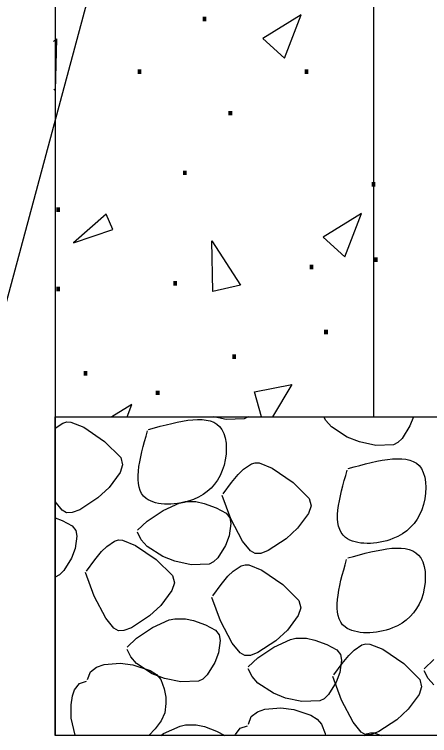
# Model space of a CAD drawing. Extents: x 638447 to 639352, y 298406 to 299000.
# Drawn here: x 638720.23 to 638735.85, y 298690 to 298717.15 of the extents above; entities that cross this region are included whole.
import ezdxf

# ---------------------------------------------------------------- set-up
doc = ezdxf.new("R2010")
doc.units = 0
doc.layers.add('2', color=7, linetype='Continuous')

msp = doc.modelspace()

# ---------------------------------------------------------------- linework, layer by layer
at = {"layer": '2'}
msp.add_line((638721.754375, 298774.004), (638721.754375, 298690.004), dxfattribs=at)
for points in [[(638727.754375, 298774.004), (638721.754375, 298774.004), (638721.754375, 298702.004), (638733.754375, 298702.004), (638733.754375, 298766.248)], [(638714.282375, 298697.684), (638717.588375, 298697.684), (638726.312375, 298730.088)], [(638721.698375, 298716.124), (638721.810375, 298716.222)], [(638721.810375, 298716.222), (638721.762375, 298714.278)], [(638721.762375, 298714.278), (638721.706375, 298714.334)], [(638729.262375, 298702.938), (638730.666375, 298703.214)], [(638730.666375, 298703.214), (638729.936375, 298702.004)], [(638729.528375, 298702.004), (638729.262375, 298702.938)], [(638724.642375, 298702.47), (638723.898375, 298702.004)], [(638724.464375, 298702.004), (638724.642375, 298702.47)], [(638722.050375, 298701.768), (638722.200375, 298701.808)], [(638722.200375, 298701.808), (638722.346375, 298701.802)], [(638722.346375, 298701.802), (638722.836375, 298701.606)], [(638728.202375, 298701.904), (638727.728375, 298702.004)], [(638728.876375, 298701.924), (638728.202375, 298701.904)], [(638729.028375, 298702.004), (638728.876375, 298701.924)], [(638731.948375, 298701.866), (638731.878375, 298702.004)], [(638732.162375, 298701.618), (638731.948375, 298701.866)], [(638735.246375, 298702.004), (638735.114375, 298701.656)], [(638721.754375, 298701.568), (638722.050375, 298701.768)], [(638722.836375, 298701.606), (638723.620375, 298701.068)], [(638732.754375, 298701.232), (638732.162375, 298701.618)], [(638735.114375, 298701.656), (638734.824375, 298701.188)], [(638723.620375, 298701.068), (638724.226375, 298700.464)], [(638733.214375, 298701.056), (638732.754375, 298701.232)], [(638733.828375, 298700.926), (638733.214375, 298701.056)], [(638734.662375, 298701.03), (638734.502375, 298700.946)], [(638734.824375, 298701.188), (638734.662375, 298701.03)], [(638734.502375, 298700.946), (638733.828375, 298700.926)], [(638724.226375, 298700.464), (638724.298375, 298700.19)], [(638724.298375, 298700.19), (638724.206375, 298699.9)], [(638728.846375, 298700.032), (638729.146375, 298700.23)], [(638729.146375, 298700.23), (638729.294375, 298700.272)], [(638729.294375, 298700.272), (638729.440375, 298700.266)], [(638729.440375, 298700.266), (638729.930375, 298700.07)], [(638724.206375, 298699.9), (638723.794375, 298699.344)], [(638728.650375, 298699.836), (638728.846375, 298700.032)], [(638729.930375, 298700.07), (638730.714375, 298699.532)], [(638728.396375, 298699.528), (638728.650375, 298699.836)], [(638723.794375, 298699.344), (638723.364375, 298698.948)], [(638728.084375, 298699.102), (638728.396375, 298699.528)], [(638730.714375, 298699.532), (638731.320375, 298698.928)], [(638722.022375, 298698.49), (638721.754375, 298698.814)], [(638723.364375, 298698.948), (638722.688375, 298698.504)], [(638726.452375, 298698.762), (638726.658375, 298698.812)], [(638726.658375, 298698.812), (638727.056375, 298698.808)], [(638727.056375, 298698.808), (638727.368375, 298698.744)], [(638728.374375, 298698.158), (638728.044375, 298699.044)], [(638731.320375, 298698.928), (638731.392375, 298698.654)], [(638725.828375, 298698.48), (638726.452375, 298698.762)], [(638727.368375, 298698.744), (638727.820375, 298698.578)], [(638727.820375, 298698.578), (638728.198375, 298698.374)], [(638731.392375, 298698.654), (638731.300375, 298698.364)], [(638722.190375, 298698.39), (638722.022375, 298698.49)], [(638722.402375, 298698.396), (638722.190375, 298698.39)], [(638722.688375, 298698.504), (638722.402375, 298698.396)], [(638725.224375, 298698.08), (638725.828375, 298698.48)], [(638728.198375, 298698.374), (638728.332375, 298698.204)], [(638731.300375, 298698.364), (638730.888375, 298697.808)], [(638721.754375, 298698.196), (638722.022375, 298698.098)], [(638722.022375, 298698.098), (638722.400375, 298697.892)], [(638724.862375, 298697.734), (638725.224375, 298698.08)], [(638728.374375, 298697.988), (638728.308375, 298697.528)], [(638728.332375, 298698.204), (638728.374375, 298697.988)], [(638728.810375, 298697.324), (638728.374375, 298698.158)], [(638722.400375, 298697.892), (638722.536375, 298697.722)], [(638722.536375, 298697.722), (638722.578375, 298697.506)], [(638730.888375, 298697.808), (638730.458375, 298697.412)], [(638722.578375, 298697.506), (638722.510375, 298697.046)], [(638725.002375, 298697.374), (638724.862375, 298697.656)], [(638728.308375, 298697.528), (638728.170375, 298697.164)], [(638723.700375, 298697.126), (638723.998375, 298697.326)], [(638723.998375, 298697.326), (638724.148375, 298697.368)], [(638724.148375, 298697.368), (638724.294375, 298697.362)], [(638724.294375, 298697.362), (638724.784375, 298697.164)], [(638725.218375, 298697.126), (638725.002375, 298697.374)], [(638729.116375, 298696.954), (638728.810375, 298697.324)], [(638730.458375, 298697.412), (638729.782375, 298696.968)], [(638722.510375, 298697.046), (638722.372375, 298696.682)], [(638723.250375, 298696.624), (638723.504375, 298696.93)], [(638723.504375, 298696.93), (638723.700375, 298697.126)], [(638724.784375, 298697.164), (638725.568375, 298696.626)], [(638725.810375, 298696.738), (638725.218375, 298697.126)], [(638728.170375, 298697.164), (638727.878375, 298696.696)], [(638729.286375, 298696.854), (638729.116375, 298696.954)], [(638729.782375, 298696.968), (638729.496375, 298696.86)], [(638722.372375, 298696.682), (638722.082375, 298696.214)], [(638725.568375, 298696.626), (638726.174375, 298696.024)], [(638726.270375, 298696.562), (638725.810375, 298696.738)], [(638727.878375, 298696.696), (638727.716375, 298696.538)], [(638729.496375, 298696.86), (638729.286375, 298696.854)], [(638722.936375, 298696.198), (638723.250375, 298696.624)], [(638726.884375, 298696.434), (638726.270375, 298696.562)], [(638727.558375, 298696.454), (638726.884375, 298696.434)], [(638727.716375, 298696.538), (638727.558375, 298696.454)], [(638728.458375, 298696.194), (638728.758375, 298696.392)], [(638728.758375, 298696.392), (638728.906375, 298696.434)], [(638728.906375, 298696.434), (638729.052375, 298696.428)], [(638729.052375, 298696.428), (638729.544375, 298696.23)], [(638722.082375, 298696.214), (638721.920375, 298696.056)], [(638723.228375, 298695.254), (638722.898375, 298696.14)], [(638728.262375, 298695.998), (638728.458375, 298696.194)], [(638729.544375, 298696.23), (638730.328375, 298695.694)], [(638721.762375, 298695.972), (638721.754375, 298695.972)], [(638721.920375, 298696.056), (638721.762375, 298695.972)], [(638726.174375, 298696.024), (638726.246375, 298695.75)], [(638728.008375, 298695.69), (638728.262375, 298695.998)], [(638726.246375, 298695.75), (638726.154375, 298695.46)], [(638727.696375, 298695.264), (638728.008375, 298695.69)], [(638730.328375, 298695.694), (638730.934375, 298695.09)], [(638726.154375, 298695.46), (638725.742375, 298694.904)], [(638723.662375, 298694.42), (638723.228375, 298695.254)], [(638727.986375, 298694.32), (638727.656375, 298695.206)], [(638730.934375, 298695.09), (638731.004375, 298694.816)], [(638725.742375, 298694.904), (638725.312375, 298694.508)], [(638731.004375, 298694.816), (638730.912375, 298694.526)], [(638725.312375, 298694.508), (638724.636375, 298694.064)], [(638730.912375, 298694.526), (638730.502375, 298693.97)], [(638723.970375, 298694.05), (638723.662375, 298694.42)], [(638725.430375, 298694.072), (638726.056375, 298694.354)], [(638726.056375, 298694.354), (638726.260375, 298694.404)], [(638726.260375, 298694.404), (638726.660375, 298694.4)], [(638726.660375, 298694.4), (638726.972375, 298694.336)], [(638726.972375, 298694.336), (638727.422375, 298694.172)], [(638728.422375, 298693.486), (638727.986375, 298694.32)], [(638724.138375, 298693.948), (638723.970375, 298694.05)], [(638724.350375, 298693.954), (638724.138375, 298693.948)], [(638724.636375, 298694.064), (638724.350375, 298693.954)], [(638724.826375, 298693.672), (638725.430375, 298694.072)], [(638727.422375, 298694.172), (638727.800375, 298693.966)], [(638727.800375, 298693.966), (638727.936375, 298693.796)], [(638730.502375, 298693.97), (638730.070375, 298693.574)], [(638724.466375, 298693.326), (638724.826375, 298693.672)], [(638727.936375, 298693.796), (638727.976375, 298693.582)], [(638730.618375, 298693.616), (638730.824375, 298693.668)], [(638730.824375, 298693.668), (638731.222375, 298693.664)], [(638731.222375, 298693.664), (638731.536375, 298693.598)], [(638727.976375, 298693.582), (638727.910375, 298693.12)], [(638728.728375, 298693.116), (638728.422375, 298693.486)], [(638730.070375, 298693.574), (638729.394375, 298693.13)], [(638729.994375, 298693.334), (638730.618375, 298693.616)], [(638731.536375, 298693.598), (638731.986375, 298693.434)], [(638731.986375, 298693.434), (638732.364375, 298693.228)], [(638733.012375, 298693.216), (638733.310375, 298693.414)], [(638733.310375, 298693.414), (638733.458375, 298693.456)], [(638733.458375, 298693.456), (638733.606375, 298693.45)], [(638733.606375, 298693.45), (638734.096375, 298693.252)], [(638724.606375, 298692.966), (638724.466375, 298693.248)], [(638727.910375, 298693.12), (638727.772375, 298692.756)], [(638728.898375, 298693.016), (638728.728375, 298693.116)], [(638729.394375, 298693.13), (638729.110375, 298693.02)], [(638729.390375, 298692.934), (638729.994375, 298693.334)], [(638732.364375, 298693.228), (638732.498375, 298693.058)], [(638732.814375, 298693.02), (638733.012375, 298693.216)], [(638734.096375, 298693.252), (638734.880375, 298692.716)], [(638724.822375, 298692.718), (638724.606375, 298692.966)], [(638729.110375, 298693.02), (638728.898375, 298693.016)], [(638729.028375, 298692.59), (638729.390375, 298692.934)], [(638732.540375, 298692.844), (638732.474375, 298692.384)], [(638732.498375, 298693.058), (638732.540375, 298692.844)], [(638732.560375, 298692.712), (638732.814375, 298693.02)], [(638735.656375, 298692.518), (638736.016375, 298692.864)], [(638723.084375, 298692.406), (638723.316375, 298692.58)], [(638723.316375, 298692.58), (638723.600375, 298692.676)], [(638723.600375, 298692.676), (638724.202375, 298692.724)], [(638724.202375, 298692.724), (638724.684375, 298692.668)], [(638724.684375, 298692.668), (638725.330375, 298692.456)], [(638725.414375, 298692.332), (638724.822375, 298692.718)], [(638727.772375, 298692.756), (638727.482375, 298692.288)], [(638732.248375, 298692.286), (638732.560375, 298692.712)], [(638734.880375, 298692.716), (638735.486375, 298692.112)], [(638722.978375, 298692.112), (638723.084375, 298692.406)], [(638725.330375, 298692.456), (638725.572375, 298692.3)], [(638725.872375, 298692.156), (638725.414375, 298692.332)], [(638725.572375, 298692.3), (638725.732375, 298692.112)], [(638727.482375, 298692.288), (638727.320375, 298692.13)], [(638729.170375, 298692.23), (638729.028375, 298692.512)], [(638732.474375, 298692.384), (638732.336375, 298692.02)], [(638735.796375, 298692.158), (638735.656375, 298692.44)], [(638722.674375, 298691.96), (638722.940375, 298692.054)], [(638725.732375, 298692.112), (638725.868375, 298691.762)], [(638726.488375, 298692.026), (638725.872375, 298692.156)], [(638727.160375, 298692.046), (638726.488375, 298692.026)], [(638727.320375, 298692.13), (638727.160375, 298692.046)], [(638729.384375, 298691.982), (638729.170375, 298692.23)], [(638732.336375, 298692.02), (638732.046375, 298691.552)], [(638732.538375, 298691.342), (638732.210375, 298692.228)], [(638735.486375, 298692.112), (638735.556375, 298691.838)], [(638736.012375, 298691.912), (638735.796375, 298692.158)], [(638722.492375, 298691.722), (638722.674375, 298691.96)], [(638725.868375, 298691.762), (638725.922375, 298691.454)], [(638729.976375, 298691.594), (638729.384375, 298691.982)], [(638735.556375, 298691.838), (638735.464375, 298691.548)], [(638722.356375, 298691.156), (638722.412375, 298691.502)], [(638722.412375, 298691.502), (638722.492375, 298691.722)], [(638730.436375, 298691.418), (638729.976375, 298691.594)], [(638732.046375, 298691.552), (638731.884375, 298691.392)], [(638735.464375, 298691.548), (638735.054375, 298690.992)], [(638725.930375, 298691.216), (638725.882375, 298690.866)], [(638725.922375, 298691.454), (638725.930375, 298691.216)], [(638731.050375, 298691.288), (638730.436375, 298691.418)], [(638731.724375, 298691.31), (638731.050375, 298691.288)], [(638731.884375, 298691.392), (638731.724375, 298691.31)], [(638732.974375, 298690.508), (638732.538375, 298691.342)], [(638722.368375, 298690.654), (638722.356375, 298691.156)], [(638729.372375, 298690.898), (638729.656375, 298690.994)], [(638729.656375, 298690.994), (638730.258375, 298691.042)], [(638730.258375, 298691.042), (638730.740375, 298690.986)], [(638730.740375, 298690.986), (638731.386375, 298690.774)], [(638735.054375, 298690.992), (638734.622375, 298690.596)], [(638722.516375, 298690.018), (638722.368375, 298690.654)], [(638725.882375, 298690.866), (638725.750375, 298690.562)], [(638729.034375, 298690.43), (638729.140375, 298690.724)], [(638729.140375, 298690.724), (638729.372375, 298690.898)], [(638731.386375, 298690.774), (638731.628375, 298690.618)], [(638725.750375, 298690.562), (638725.524375, 298690.252)], [(638726.466375, 298690.358), (638726.672375, 298690.408)], [(638726.672375, 298690.408), (638727.070375, 298690.404)], [(638727.070375, 298690.404), (638727.382375, 298690.34)], [(638731.628375, 298690.618), (638731.788375, 298690.43)], [(638731.788375, 298690.43), (638731.924375, 298690.08)], [(638733.280375, 298690.138), (638732.974375, 298690.508)], [(638734.622375, 298690.596), (638733.948375, 298690.152)], [(638725.524375, 298690.252), (638725.288375, 298690.004)], [(638725.842375, 298690.076), (638726.466375, 298690.358)], [(638727.382375, 298690.34), (638727.834375, 298690.176)], [(638727.834375, 298690.176), (638728.148375, 298690.004)], [(638728.548375, 298690.04), (638728.730375, 298690.28)], [(638728.730375, 298690.28), (638728.996375, 298690.372)], [(638733.450375, 298690.038), (638733.280375, 298690.138)], [(638733.480375, 298690.07), (638733.628375, 298690.112)], [(638733.628375, 298690.112), (638733.774375, 298690.106)], [(638733.948375, 298690.152), (638733.662375, 298690.042)], [(638722.524375, 298690.004), (638722.516375, 298690.018)], [(638725.734375, 298690.004), (638725.842375, 298690.076)], [(638728.534375, 298690.004), (638728.548375, 298690.04)], [(638731.924375, 298690.08), (638731.938375, 298690.004)], [(638733.380375, 298690.004), (638733.480375, 298690.07)], [(638733.662375, 298690.042), (638733.450375, 298690.038)], [(638733.774375, 298690.106), (638734.028375, 298690.004)]]:
    msp.add_lwpolyline(points, dxfattribs=at)
for points in [[(638731.014375, 298717.134), (638729.574375, 298716.234), (638730.390375, 298715.502)], [(638733.294375, 298709.658), (638731.854375, 298708.758), (638732.670375, 298708.026)], [(638723.934375, 298709.046), (638723.682375, 298709.622), (638722.446375, 298708.554)], [(638728.734375, 298706.958), (638727.690375, 298706.718), (638727.654375, 298708.626)], [(638721.754375, 298690.004), (638721.754375, 298702.004), (638793.754375, 298702.004), (638793.754375, 298690.004)]]:
    msp.add_lwpolyline(points, close=True, dxfattribs=at)
for points in [[(638725.278375, 298701.528), (638728.032375, 298701.528), (638728.052375, 298699.976), (638726.966375, 298698.892), (638725.182375, 298698.93), (638725.240375, 298701.47)], [(638732.790375, 298700.054), (638735.544375, 298700.054), (638735.562375, 298698.504), (638734.476375, 298697.418), (638732.694375, 298697.456), (638732.752375, 298699.996)], [(638732.772375, 298696.69), (638735.524375, 298696.69), (638735.544375, 298695.14), (638734.458375, 298694.054), (638732.674375, 298694.092), (638732.732375, 298696.632)]]:
    msp.add_spline(points, degree=3, dxfattribs=at)

# ---------------------------------------------------------------- texts
for p in [(638727.174375, 298716.882), (638724.726375, 298714.902), (638731.014375, 298714.902), (638728.146375, 298713.342), (638726.430375, 298711.098), (638733.534375, 298710.666), (638721.666375, 298709.706), (638733.618375, 298707.834), (638731.206375, 298707.558), (638726.070375, 298706.934), (638721.666375, 298706.73), (638731.746375, 298705.11), (638728.290375, 298704.174), (638722.698375, 298703.55), (638725.410375, 298702.818)]:
    msp.add_text('.', height=1.116, dxfattribs=at).set_placement(p)

doc.saveas('drawing.dxf')
